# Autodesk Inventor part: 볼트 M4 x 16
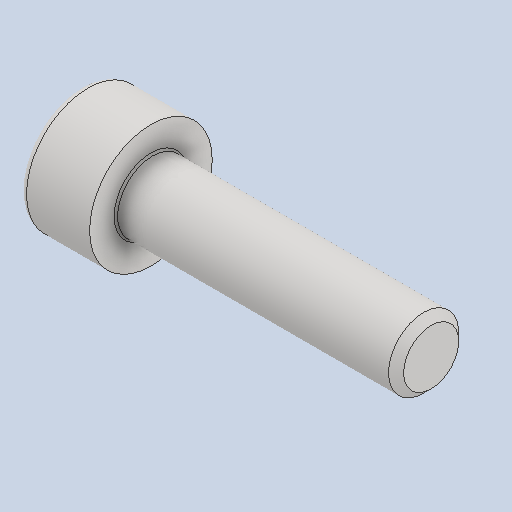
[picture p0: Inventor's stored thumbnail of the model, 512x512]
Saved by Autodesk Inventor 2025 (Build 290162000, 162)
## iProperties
Created: 2024-07
Part Number: 볼트 M4 x 16
Material: 스테인리스강
Description: 6각 소켓 머리 캡 나사
Document SubType Name: Modeling
Designer: onair
Density: 8.08 g/cm^3
Appearance: 기본값
Author: jhkim
Sending System: Autodesk Inventor 2025
Preprocessor: ST-DEVELOPER v20
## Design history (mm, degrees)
feature "Solid1"
node "솔리드1"
